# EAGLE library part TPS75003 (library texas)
Triple-Supply Power Management IC for Powering FPGAs and DSPs Source: http://focus.ti.com/lit/ds/symlink/tps75003.pdf
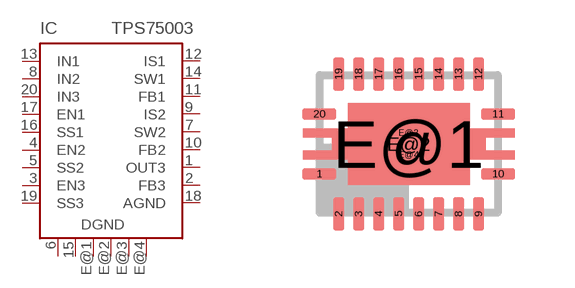
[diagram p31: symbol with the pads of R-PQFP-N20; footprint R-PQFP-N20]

Designator prefix IC

## TPS75003 (MPN: TPS75003RHLT; OC_FARNELL: 9969187; OC_NEWARK: 93K0913)  [R-PQFP-N20]
1  OUT3  out
2  FB3  in
3  EN3  in
4  EN2  in
5  SS2  in
6  DGND  pwr
7  SW2  in
8  IN2  in
9  IS2  in
10  FB2  in
11  FB1  in
12  IS1  in
13  IN1  in
14  SW1  in
15  DGND  pwr
16  SS1  in
17  EN1  in
18  AGND  pwr
19  SS3  in
20  IN3  in
E@1  DGND  pwr
E@2  DGND  pwr
E@3  DGND  pwr
E@4  DGND  pwr

## Footprint R-PQFP-N20 (pad centres in mm)
PQFP20 RHL PACKAGE 4.5mm x 3.5mm QFN Source: http://focus.ti.com/lit/ds/symlink/tps75003.pdf
smd 0.85 x 0.28: 1 -2.235,-0.75; 10 2.235,-0.75; 11 2.235,0.75; 20 -2.235,0.75
smd 0.28 x 0.85: 2 -1.75,-1.75; 3 -1.25,-1.75; 4 -0.75,-1.75; 5 -0.25,-1.75; 6 0.25,-1.75; 7 0.75,-1.75; 8 1.25,-1.75; 9 1.75,-1.75; 12 1.75,1.75; 13 1.25,1.75; 14 0.75,1.75; 15 0.25,1.75; 16 -0.25,1.75; 17 -0.75,1.75; 18 -1.25,1.75; 19 -1.75,1.75
smd 3.05 x 2.05: E@1 0,0
smd 3.85 x 0.5: E@2 0,0
smd 5.3 x 0.23: E@3 0,0.275; E@4 0,-0.275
